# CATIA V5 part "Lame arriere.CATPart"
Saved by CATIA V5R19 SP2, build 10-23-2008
Part number: Lame arrière
Bounding box of the stored display mesh (mm): x 0 to 5, y -200 to 200, z 0 to 15
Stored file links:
  C:\Users\Romain\Documents\IFMA\2A\cours\S3\Projet CFAO-IAO\CFAO\Catia\Organe de fixation\Lame arriere.CATPart
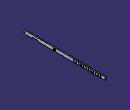
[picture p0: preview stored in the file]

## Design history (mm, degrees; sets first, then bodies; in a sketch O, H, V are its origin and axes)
Body1 (main body)
  Sketch1 on yz-plane, origin (0, 0, 0), H (0, 1, 0), V (0, 0, 1)
    point P1 (-200, 0)
    line L1 (-200, 0) -> (200, 0)
    line L2 (200, 0) -> (200, 15)
    line L3 (200, 15) -> (-200, 15)
    line L4 (-200, 15) -> (-200, 0)
    length L1 = 400
    length L2 = 15
    distance V L4 = 200
    coincidence: P1 H
    horizontal: L1 H, L3 H
    vertical: L2 V, L4 V
  Pad1: profile Sketch1, direction (1, 0, 0), length 5
  Sketch2 on end face of Pad1, origin (5, 0, 0), H (0, 1, 0), V (0, 0, 1)
    point P1 (176, 10)
    line L1 (180, 11.5) -> (180, 10)
    point P2 (180, 11.5)
    point P3 (180, 10)
    arc A1 centre (178, 10) radius 2 from (176, 10) to (180, 10) ccw
    point P5 (180, 10)
    line L2 (176, 10) -> (176, 11.5)
    point P6 (176, 10)
    point P7 (176, 11.5)
    arc A2 centre (178, 11.5) radius 2 from (180, 11.5) to (176, 11.5) ccw
    point P8 (178, 11.5)
    point P9 (180, 11.5)
    point P10 (176, 11.5)
    reference intersected line E1 (200, 15) -> (200, 0) from face of Pad1
    reference intersected line E2 (-175, 15) -> (175, 15) from face of Pad1
    length L2 = 1.5
    radius A2 = 2
    radius A1 = 2
    distance E1 L1 = 20
    distance P8 E2 = 3.5
    vertical: L1 V
    tangency: A1 L1, L2 A1, A2 L1, L2 A2
    coincidence: P5 P3, P6 A1, P1 P6, P9 L1, P10 P7, P9 P2
  Pocket1: profile Sketch2, direction (-1, 0, 0), through (limit type 3)
  RectPattern1: of Pocket1, direction 1 instances 2, spacing -6.5, along edge [face of Pad1 from Sketch1.L2 | end face of Pad1], direction 2 instances 12, spacing 12, along edge [face of Pad1 from Sketch1.L3 | end face of Pad1]
  Sketch3 "Esquisse.3" on end face of Pad1, origin (5, 0, 0), H (0, 1, 0), V (0, 0, 1)
    point P1 (-160, 0)
    line L1 (-160, 0) -> (-130, 0)
    line L2 (-130, 0) -> (-130, 5)
    line L3 (-130, 5) -> (-160, 5)
    line L4 (-160, 5) -> (-160, 0)
    line L5 (-200, 10) -> (-195, 10)
    line L6 (-195, 10) -> (-195, 5)
    line L7 (-195, 5) -> (-200, 5)
    line L8 (-200, 5) -> (-200, 10)
    reference projected line E1 (-200, 15) -> (-200, 0) from edge [face of Pad1 from Sketch1.L4 | end face of Pad1]
    reference projected line E2 (-200, 15) -> (-200, 0) from edge [face of Pad1 from Sketch1.L4 | end face of Pad1]
    reference projected line E3 (200, 15) -> (-200, 15) from edge [face of Pad1 from Sketch1.L3 | end face of Pad1]
    length L7 = 5
    distance E2 L4 = 40
    length L1 = 30
    length L2 = 5
    distance L5 E3 = 5
    length L6 = 5
    coincidence: P1 H, L8 E1
    horizontal: L1 H, L3 H, L5 H, L7 H
    vertical: L2 V, L4 V, L6 V, L8 V
  Pocket2: profile Sketch3, direction (-1, 0, 0), through (limit type 3)
  Sketch4 "Esquisse.4" on end face of Pad1, origin (5, -24.6916, 7.88), H (0, 1, 0), V (0, 0, 1)
    point P1 (-25.3084, -0.38)
    reference projected line E1 (224.6916, 7.12) -> (-175.3084, 7.12) from edge [face of Pad1 from Sketch1.L3 | end face of Pad1]
    reference projected line E2 (-175.3084, 7.12) -> (-175.3084, -7.88) from edge [face of Pad1 from Sketch1.L4 | end face of Pad1]
    distance P1 E1 = 7.5
    distance P1 E2 = 150
  Hole1: placed by Sketch4, at (5, -50, 7.5) direction (-1, 0, 0), diameter 8, through (limit type 3)
  Sketch5 "Esquisse.5" on end face of Pad1, origin (5, -59.8292, 8.1976), H (0, 1, 0), V (0, 0, 1)
    point P1 (9.8292, -0.6976)
    reference projected line E1 (259.8292, 6.8024) -> (-140.1708, 6.8024) from edge [face of Pad1 from Sketch1.L3 | end face of Pad1]
    reference projected line E2 (-140.1708, 6.8024) -> (-140.1708, -8.1976) from edge [face of Pad1 from Sketch1.L4 | end face of Pad1]
    distance P1 E1 = 7.5
    distance P1 E2 = 150
  Hole2: placed by Sketch5, at (5, -50, 7.5) direction (-1, 0, 0), diameter 12, depth 2
  Fillet1: radius 2, on edge [face of Pad1 from Sketch1.L3 | face of Pad1 from Sketch1.L2]; edge [face of Pad1 from Sketch1.L2 | face of Pad1 from Sketch1.L1]; edge [face of Pad1 from Sketch1.L4 | face of Pad1 from Sketch1.L3]; edge [face of Pad1 from Sketch1.L1 | face of Pad1 from Sketch1.L4]
  Fillet2: radius 1, on edge [face of Pocket2 from Sketch3.L4 | face of Pocket2 from Sketch3.L3]; edge [face of Pocket2 from Sketch3.L3 | face of Pocket2 from Sketch3.L2]; edge [face of Pocket2 from Sketch3.L5 | face of Pocket2 from Sketch3.L6]; edge [face of Pocket2 from Sketch3.L6 | face of Pocket2 from Sketch3.L7]; edge [face of Pad1 from Sketch1.L1 | face of Pocket2 from Sketch3.L4]; edge [face of Pocket2 from Sketch3.L2 | face of Pad1 from Sketch1.L1]; edge [face of Pad1 from Sketch1.L4 | face of Pocket2 from Sketch3.L5]; edge [face of Pocket2 from Sketch3.L7 | face of Pad1 from Sketch1.L4]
